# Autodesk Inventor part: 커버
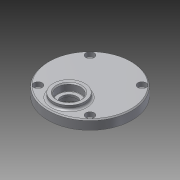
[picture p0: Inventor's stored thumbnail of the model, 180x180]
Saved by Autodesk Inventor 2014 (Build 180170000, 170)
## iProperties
Created: 2015-07
Part Number: 커버
Material: 알루미늄 6061
Document SubType Name: Modeling
Designer: Administrator
Mass: 113.906 g
Surface Area: 144.874 cm^2
Volume: 42.0316 cm^3
Density: 2.71 g/cm^3
Appearance: 알루미늄 - 평지
Author: Administrator
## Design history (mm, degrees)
sketch "스케치1"
  geometry: C1 r 40 at (0, 0); 1 further point
  constraints: 1 centre point, 1 coincident
  dimensions: "d0" = 80 diameter of C1
extrude "돌출1" new body sketch "스케치1" distance "d1" = 9; taper "d2" = 0 deg
sketch "스케치2"
  geometry: C1 r 40 at (0, 0) reference; C2 r 14 at (0, 11); C3 r 14 at (0, -20)
  constraints: 2 centre point, 2 vertical alignment
  dimensions: "d3" = 28 diameter of C2; "d4" = 28 diameter of C3; "d5" = 11 distance of C1.centre C2.centre; "d6" = 20 distance of C3.centre C1.centre
extrude "돌출2" join sketch "스케치2" distance "d7" = 3; taper "d8" = 0 deg
sketch "스케치3"
  geometry: C1 r 14 at (0, 0) reference; C2 r 14 at (0, -31) reference; C3 r 11 at (0, 0); C4 r 11 at (0, -31); 1 further point
  constraints: 2 centre point, 2 coincident
  dimensions: "d9" = 22 diameter of C3; "d10" = 22 diameter of C4
extrude "돌출3" cut sketch "스케치3" distance "d11" = 7; taper "d12" = 0 deg
sketch "스케치4"
  geometry: C1 r 9 at (0, 0); 2 further points
  constraints: 1 centre point, 1 coincident, 1 vertical alignment
  dimensions: "d13" = 18 diameter of C1
extrude "돌출4" cut sketch "스케치4" distance "d14" = 1; taper "d15" = 0 deg
sketch "스케치5"
  geometry: C1 r 11 at (0, 0) reference; C2 r 7.5 at (0, 0); 1 further point
  constraints: 1 centre point, 1 coincident
  dimensions: "d16" = 15 diameter of C2
extrude "돌출5" cut sketch "스케치5" stored distance "d17" = 1; taper "d18" = 0 deg
sketch "스케치6"
  geometry: C1 r 7.5 at (0, -20) reference; C2 r 15 at (0, -20)
  constraints: 1 centre point, 1 coincident
  dimensions: "d19" = 30 diameter of C2
extrude "돌출6" join sketch "스케치6" distance "d20" = 4; taper "d21" = 0 deg
sketch "스케치7"
  geometry: C1 r 7.5 at (0, 0) reference; C2 r 15 at (0, 0) reference; C3 r 11 at (0, 0); 1 further point
  constraints: 1 centre point, 1 coincident
  dimensions: "d22" = 22 diameter of C3
extrude "돌출7" cut sketch "스케치7" distance "d23" = 7; taper "d24" = 0 deg
sketch "스케치8"
  geometry: L1 (-24.749, 24.749)-(0, 0); L2 (0, 0)-(0, 35); C1 r 40 at (0, 0) reference; C2 r 4 at (-24.749, 24.749); A1 r 35 centre (0, 0) between (-24.749, 24.749) and (0, 35)
  constraints: 4 end point, 2 centre point, 2 point on circle, 1 coincident, 1 vertical
  dimensions: "d25" = 70 diameter of A1; "d26" = 8 diameter of C2; "d27" = 45 deg angle of L2 L1
extrude "돌출8" cut sketch "스케치8" distance "d28" = 4.4; taper "d29" = 0 deg
sketch "스케치9"
  geometry: C1 r 4 at (0, 0) reference; C2 r 2.25 at (0, 0); 1 further point
  constraints: 1 centre point, 1 coincident
  dimensions: "d30" = 4.5 diameter of C2
extrude "돌출9" cut sketch "스케치9" stored distance "d31" = 4.4; taper "d32" = 0 deg
chamfer "모따기1" distance "d36" = 1; stored, may be unused: second distance "d37" = 2, angle "d38" = 45 deg
fillet "모깎기1" dims "d39" = 2
fillet "모깎기2" dims "d40" = 2
fillet "모깎기3" dims "d41" = 0.3
chamfer "모따기2" distance "d42" = 1; stored, may be unused: second distance "d43" = 2, angle "d44" = 45 deg
node "솔리드1"
pattern_circular "원형 패턴1" dims angle "d34" = 360 deg
node "투영된 루프1"
